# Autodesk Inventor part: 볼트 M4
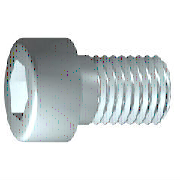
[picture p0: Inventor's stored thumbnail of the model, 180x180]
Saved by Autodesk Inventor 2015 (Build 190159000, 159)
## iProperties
IsCustomPart: 0
Created: 2014-10
Part Number: 볼트 M4
Material: 강철, 연강
Description: 6각머리 태핑 나사
Document SubType Name: Modeling
Standard: KS B 1003
Designer: KYOUNG IL JANG
Standards Organization: KS
Language: ko-KR
Size Designation: M 4 x 10
Categories: <MemberInstance><Categories><Category DisplayName="조임쇠" InternalName="e4da775c-781d-43d5-af7c-5136215cf5a6" Mnemonic="FSTN"><Category DisplayName="볼트" InternalN
Density: 7.86 g/cm^3
Mass: 2.0371 g
Surface Area: 3.0572 cm^2
Volume: 0.259174 cm^3
Appearance: 강철 - 광택
Author: SeoGD™ [www.esajin.kr]
Revision Number: 1
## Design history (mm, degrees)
sketch "스케치1"
  geometry: L1 (-1, 0)-(10, 0); L2 (10, 0)-(10, 2); L3 (10, 2)-(1.75, 2); L4 (1.75, 2)-(1.32, 2); L5 (1.32, 2)-(0, 2); L6 (0, 2)-(0, 3.5); L7 (0, 3.5)-(-4, 3.5); L8 (-4, 3.5)-(-4, 1.732); L9 (-4, 1.732)-(-2, 1.732); L10 (-2, 1.732)-(-1, 0); L11 (-6.8, 0)-(12.8, 0) reference; L12 (0, -0.7)-(0, 4.2) reference; L13 (1.75, 2)-(0, 2)
  constraints: 22 end point, 6 parallel, 2 collinear, 2 perpendicular, 1 horizontal, 1 point on line
  dimensions: "d1" = 8.25 distance from line of L3.end L2 (= GEL); "d2" = 0.42952 distance of L4.end L3.end (computed from GAL); "d3" = 4 distance between parallel lines of L8 L6 (= KOH); "d4" = 2 distance of L8.end L9.end (= INTI); "d5" = 60 deg angle of L10 L1; "d6" = 4 diameter of L3 L1 (= GD); "d7" = 4 diameter of L5 L1 (= BDM); "d8" = 3.4641 diameter of L9 L1 (= 1.1547 x SW); "d9" = 7 diameter of L7 L1 (= KOD); "d26" = 10 distance between parallel lines of L12 L2 (= NLG)
revolve "본체" sketch "스케치1" stored, may be unused: angle "d10" = 90 deg
sketch "스케치2"
  geometry: L1 (0, -4.9)-(0, 4.9) reference; L2 (-4.9, 0)-(4.9, 0) reference; L3 (1.732, 0)-(0.866, -1.5); L4 (0.866, -1.5)-(-0.866, -1.5); L5 (-0.866, -1.5)-(-1.732, 0); L6 (-1.732, 0)-(-0.866, 1.5); L7 (-0.866, 1.5)-(0.866, 1.5); L8 (0.866, 1.5)-(1.732, 0); 2 further points
  constraints: 12 end point, 1 coincident, 1 horizontal alignment, 1 point on line, 12 other
extrude "슬롯" join sketch "스케치2" stored distance "d11" = 10; taper "d12" = 0 deg
workplane "Work Plane1"
fillet "Fillet2" dims "d30" = 0.1 (= R)
body "Solid1"
fillet "모깎기1" dims "d17" = 0.4 (= RR)
feature "스레드" dims "d13" = 8.25 (= GEL), "d14" = 0
chamfer "모따기1" distance "d15" = 0.42941 (= -0.5 x SPD + 0.5 x GD); stored, may be unused: second distance "d16" = 0.42941 (= GUL), angle "d27" = 45 deg
other parameters: "GD" = 4 (= NND) [user parameter; used in 2 equation terms], "NLG" = 10 [user parameter; used in 1 equation term], "GEL" = 8.25 [user parameter; used in 2 equation terms], "KOD" = 7 [user parameter; used in 1 equation term], "KOH" = 4 [user parameter; used in 1 equation term], "INTI" = 2 [user parameter; used in 1 equation term], "GAL" = 0.42941 (= 0.61345 x PTC) [user parameter; used in 1 equation term], "GUL" = 0.42941 (= 0.61345 x PTC) [user parameter; used in 1 equation term], "BDM" = 4 (= NND) [user parameter; used in 1 equation term], "SW" = 3 [user parameter; used in 2 equation terms], "RR" = 0.4 [user parameter; used in 1 equation term], "SPD" = 3.14117 (= NND - 1.2269 x PTC) [user parameter; used in 1 equation term], "d19" = 0, "d28" = 0, "d29" = 0, "R" = 0.1 [user parameter; used in 1 equation term], "PHH" = 0.2 [user parameter], "GD1" = 3.14117 (= THREADDIA - 1.2269 x PTC) [user parameter], "THREADDIA" = 4 [user parameter; used in 1 equation term], "FAWI" = 45 deg [user parameter], "TPU" = 14.28571 (computed from PTC) [user parameter], "PTC" = 0.7 [user parameter; used in 5 equation terms], "NND" = 4 [user parameter; used in 3 equation terms], "TOA" = 30 deg [user parameter], "E0" = 3.465 (= 1.155 x SW) [user parameter]
